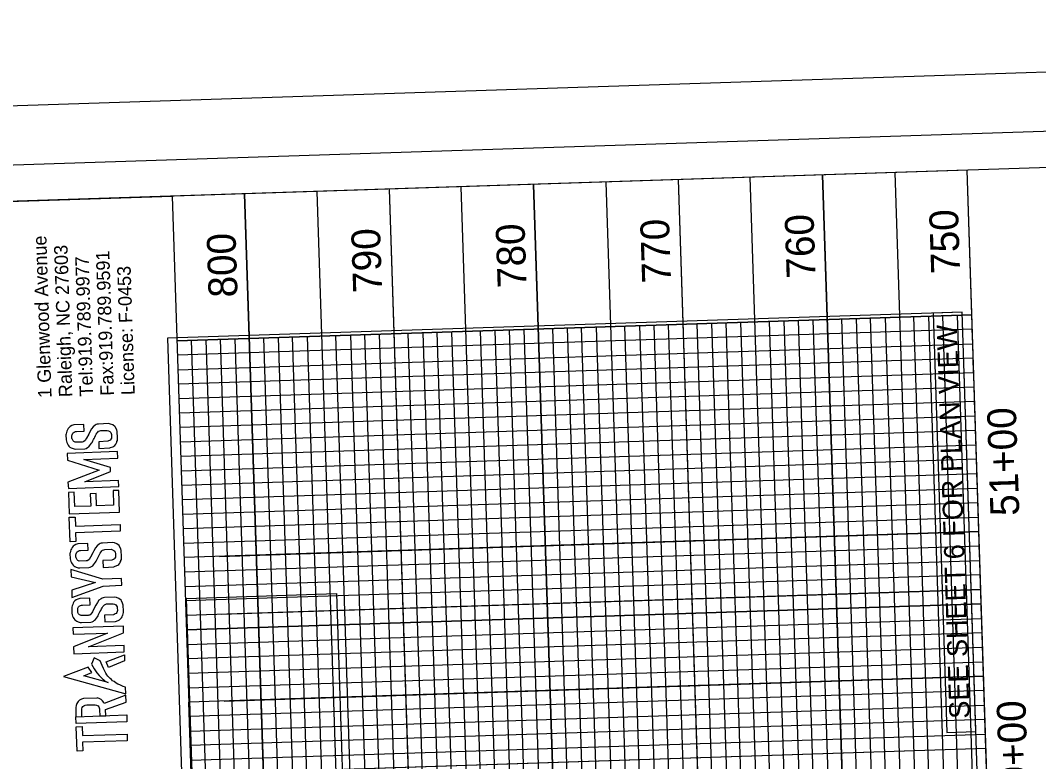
# Model space of a CAD drawing. Extents: x 1627318 to 1628473, y 762308 to 764226.
# Drawn here: x 1627516 to 1627868.1, y 763787.3 to 764043.5 of the extents above; entities that cross this region are included whole.
import ezdxf

# ---------------------------------------------------------------- set-up
doc = ezdxf.new("R2010")
doc.units = 0
for name, color, linetype in [('Exist Vertical Profile Horizontal Axis Label Major', 7, 'Continuous'), ('Exist Vertical Profile Vertical Axis Label', 7, 'Continuous'), ('Old_Level_2', 7, 'Continuous'), ('Prop DSN Text', 7, 'Continuous'), ('Prop Grid Mask', 7, 'Continuous'), ('Sheet DOT Grid CELL', 7, 'Continuous'), ('Sheet Layout Profile Border Port 1', 7, 'Continuous'), ('Sheet Plot Border Inside CELL', 7, 'Continuous'), ('Sheet Plot Border Outside CELL', 7, 'Continuous'), ('Sheet Profile CELL', 7, 'Continuous'), ('Sheet Profile Grid Major CELL', 7, 'Continuous'), ('Sheet Profile Grid Middle CELL', 7, 'Continuous'), ('Sheet Profile Grid Minor CELL', 7, 'Continuous')]:
    doc.layers.add(name, color=color, linetype=linetype)

msp = doc.modelspace()

# ---------------------------------------------------------------- linework, layer by layer
at = {"layer": 'Old_Level_2'}
for points in [[(1627511.12, 763780.74), (1627504.58, 763980.62), (1627568.5, 763982.71), (1627575.04, 763782.83)], [(1627538.04, 763901.44), (1627537.96, 763903.75), (1627534.48, 763903.63), (1627533.78, 763903.41), (1627533.2, 763903.11), (1627532.82, 763902.8), (1627532.48, 763902.42), (1627532.22, 763901.97), (1627532.06, 763901.54), (1627532.06, 763901.54), (1627531.88, 763901.08), (1627531.77, 763900.59), (1627531.7, 763900.27), (1627531.8, 763898.52), (1627531.9, 763897.99), (1627532, 763897.54), (1627532.25, 763897.09), (1627532.48, 763896.69), (1627532.77, 763896.31), (1627533.1, 763896.01), (1627533.47, 763895.78), (1627533.87, 763895.59), (1627534.58, 763895.36), (1627535.09, 763895.33), (1627538.26, 763895.43), (1627538.73, 763895.56), (1627539.22, 763895.81), (1627539.62, 763896.11), (1627539.92, 763896.42), (1627540.25, 763896.88), (1627540.58, 763897.34), (1627540.79, 763897.63), (1627541, 763898.12), (1627541.21, 763898.61), (1627541.45, 763899.01), (1627541.72, 763899.46), (1627541.97, 763900), (1627542.18, 763900.44), (1627542.48, 763900.88), (1627542.76, 763901.2), (1627542.99, 763901.46), (1627543.47, 763901.62), (1627543.76, 763901.73), (1627546, 763901.77), (1627546.49, 763901.62), (1627546.92, 763901.39), (1627547.22, 763901.07), (1627547.39, 763900.72), (1627547.47, 763900.38), (1627547.53, 763899.42), (1627547.45, 763899.1), (1627547.26, 763898.76), (1627547.08, 763898.43), (1627546.75, 763898.28), (1627546.42, 763898.12), (1627546.16, 763898), (1627543.05, 763897.86), (1627543.15, 763895.53), (1627546.86, 763895.69), (1627547.14, 763895.82), (1627547.99, 763896.12), (1627548.28, 763896.3), (1627548.59, 763896.56), (1627548.95, 763896.96), (1627549.13, 763897.27), (1627549.3, 763897.71), (1627549.36, 763897.87), (1627549.53, 763898.3), (1627549.56, 763898.84), (1627549.59, 763899.23), (1627549.47, 763901.37), (1627549.31, 763901.96), (1627548.9, 763902.78), (1627548.77, 763903.05), (1627547.96, 763903.65), (1627547.16, 763903.95), (1627546.45, 763904.09), (1627543.03, 763903.92), (1627542.56, 763903.9), (1627542.18, 763903.75), (1627541.84, 763903.55), (1627541.1, 763902.99), (1627540.56, 763902.26), (1627540.01, 763901.27), (1627539.6, 763900.51), (1627538.88, 763899.02), (1627538.34, 763898.25), (1627537.93, 763897.91), (1627537.65, 763897.82), (1627537.37, 763897.73), (1627534.94, 763897.7), (1627534.68, 763897.82), (1627534.42, 763897.93), (1627534.26, 763898.11), (1627534.06, 763898.33), (1627533.94, 763898.58), (1627533.83, 763898.84), (1627533.85, 763898.99), (1627533.78, 763899), (1627533.76, 763899.96), (1627533.86, 763900.24), (1627533.96, 763900.52), (1627534.06, 763900.8), (1627534.25, 763900.94), (1627534.52, 763901.13), (1627534.8, 763901.23), (1627535.07, 763901.33), (1627535.37, 763901.34)], [(1627543.17, 763888.07), (1627532.38, 763883.91), (1627532.55, 763881.7), (1627550, 763882.36), (1627549.92, 763884.46), (1627538.25, 763884.02), (1627547.13, 763887.58), (1627547.12, 763888.93), (1627537.89, 763891.7), (1627549.61, 763892.13), (1627549.52, 763894.41), (1627532.11, 763893.77), (1627532.2, 763891.47)], [(1627532.57, 763880.35), (1627532.81, 763872.97), (1627550.23, 763873.55), (1627549.98, 763881.02), (1627548.01, 763880.95), (1627548.18, 763875.91), (1627542.34, 763875.71), (1627542.2, 763879.93), (1627540.12, 763879.86), (1627540.27, 763875.61), (1627534.77, 763875.42), (1627534.6, 763880.43)], [(1627533.13, 763863.28), (1627532.84, 763871.75), (1627534.92, 763871.82), (1627535.02, 763868.71), (1627550.44, 763869.23), (1627550.51, 763866.88), (1627535, 763866.36), (1627535.1, 763863.39)], [(1627539.42, 763860.33), (1627539.34, 763862.64), (1627535.87, 763862.52), (1627535.17, 763862.31), (1627534.59, 763862.01), (1627534.21, 763861.69), (1627533.87, 763861.31), (1627533.6, 763860.86), (1627533.44, 763860.43), (1627533.44, 763860.43), (1627533.26, 763859.97), (1627533.15, 763859.48), (1627533.08, 763859.16), (1627533.18, 763857.41), (1627533.29, 763856.89), (1627533.38, 763856.43), (1627533.64, 763855.98), (1627533.86, 763855.58), (1627534.16, 763855.2), (1627534.48, 763854.9), (1627534.85, 763854.67), (1627535.25, 763854.48), (1627535.96, 763854.25), (1627536.48, 763854.22), (1627539.64, 763854.32), (1627540.11, 763854.45), (1627540.6, 763854.7), (1627541, 763855), (1627541.3, 763855.31), (1627541.63, 763855.77), (1627541.97, 763856.23), (1627542.18, 763856.53), (1627542.39, 763857.02), (1627542.6, 763857.51), (1627542.84, 763857.9), (1627543.11, 763858.35), (1627543.36, 763858.89), (1627543.56, 763859.33), (1627543.86, 763859.77), (1627544.15, 763860.09), (1627544.38, 763860.35), (1627544.85, 763860.52), (1627545.15, 763860.62), (1627547.38, 763860.66), (1627547.87, 763860.51), (1627548.3, 763860.28), (1627548.6, 763859.96), (1627548.78, 763859.61), (1627548.86, 763859.27), (1627548.91, 763858.32), (1627548.83, 763857.99), (1627548.65, 763857.65), (1627548.47, 763857.32), (1627548.13, 763857.17), (1627547.8, 763857.01), (1627547.54, 763856.89), (1627544.43, 763856.75), (1627544.54, 763854.42), (1627548.24, 763854.58), (1627548.52, 763854.71), (1627549.37, 763855.01), (1627549.66, 763855.19), (1627549.97, 763855.46), (1627550.33, 763855.85), (1627550.51, 763856.16), (1627550.68, 763856.6), (1627550.74, 763856.76), (1627550.91, 763857.19), (1627550.95, 763857.73), (1627550.97, 763858.12), (1627550.85, 763860.26), (1627550.69, 763860.85), (1627550.29, 763861.67), (1627550.15, 763861.94), (1627549.34, 763862.54), (1627548.54, 763862.85), (1627547.83, 763862.98), (1627544.41, 763862.81), (1627543.94, 763862.79), (1627543.57, 763862.65), (1627543.22, 763862.44), (1627542.48, 763861.88), (1627541.95, 763861.15), (1627541.4, 763860.16), (1627540.98, 763859.4), (1627540.26, 763857.91), (1627539.72, 763857.14), (1627539.31, 763856.8), (1627539.03, 763856.71), (1627538.75, 763856.63), (1627536.32, 763856.59), (1627536.06, 763856.71), (1627535.8, 763856.82), (1627535.64, 763857), (1627535.44, 763857.22), (1627535.33, 763857.48), (1627535.21, 763857.73), (1627535.23, 763857.88), (1627535.16, 763857.89), (1627535.14, 763858.85), (1627535.24, 763859.13), (1627535.34, 763859.41), (1627535.44, 763859.69), (1627535.63, 763859.83), (1627535.91, 763860.02), (1627536.18, 763860.12), (1627536.45, 763860.23), (1627536.76, 763860.23)], [(1627533.7, 763846.54), (1627533.79, 763844), (1627544.55, 763847.97), (1627551.08, 763848.22), (1627550.99, 763850.61), (1627544.51, 763850.36), (1627533.43, 763853.66), (1627533.58, 763851.17), (1627541.99, 763849.13)], [(1627540.05, 763841.47), (1627539.98, 763843.78), (1627536.5, 763843.66), (1627535.8, 763843.44), (1627535.22, 763843.14), (1627534.84, 763842.83), (1627534.5, 763842.45), (1627534.23, 763842), (1627534.07, 763841.57), (1627534.07, 763841.57), (1627533.9, 763841.11), (1627533.79, 763840.62), (1627533.72, 763840.3), (1627533.81, 763838.55), (1627533.92, 763838.02), (1627534.01, 763837.57), (1627534.27, 763837.12), (1627534.49, 763836.72), (1627534.79, 763836.33), (1627535.11, 763836.04), (1627535.49, 763835.81), (1627535.89, 763835.62), (1627536.59, 763835.39), (1627537.11, 763835.36), (1627540.28, 763835.46), (1627540.75, 763835.59), (1627541.23, 763835.84), (1627541.64, 763836.14), (1627541.94, 763836.45), (1627542.27, 763836.91), (1627542.6, 763837.37), (1627542.81, 763837.66), (1627543.02, 763838.15), (1627543.23, 763838.64), (1627543.47, 763839.04), (1627543.74, 763839.49), (1627543.99, 763840.03), (1627544.2, 763840.47), (1627544.5, 763840.91), (1627544.78, 763841.23), (1627545.01, 763841.49), (1627545.49, 763841.65), (1627545.78, 763841.76), (1627548.02, 763841.8), (1627548.51, 763841.65), (1627548.94, 763841.42), (1627549.24, 763841.1), (1627549.41, 763840.75), (1627549.49, 763840.41), (1627549.54, 763839.45), (1627549.46, 763839.13), (1627549.28, 763838.79), (1627549.1, 763838.46), (1627548.77, 763838.31), (1627548.44, 763838.15), (1627548.18, 763838.03), (1627545.07, 763837.89), (1627545.17, 763835.56), (1627548.88, 763835.72), (1627549.16, 763835.85), (1627550.01, 763836.15), (1627550.29, 763836.33), (1627550.6, 763836.59), (1627550.97, 763836.99), (1627551.15, 763837.3), (1627551.32, 763837.74), (1627551.38, 763837.9), (1627551.55, 763838.33), (1627551.58, 763838.87), (1627551.61, 763839.26), (1627551.48, 763841.4), (1627551.32, 763841.99), (1627550.92, 763842.8), (1627550.79, 763843.08), (1627549.98, 763843.68), (1627549.18, 763843.98), (1627548.46, 763844.11), (1627545.05, 763843.95), (1627544.57, 763843.93), (1627544.2, 763843.78), (1627543.85, 763843.58), (1627543.11, 763843.02), (1627542.58, 763842.29), (1627542.03, 763841.3), (1627541.61, 763840.54), (1627540.9, 763839.05), (1627540.36, 763838.28), (1627539.95, 763837.94), (1627539.67, 763837.85), (1627539.39, 763837.76), (1627536.95, 763837.73), (1627536.7, 763837.85), (1627536.44, 763837.96), (1627536.28, 763838.13), (1627536.08, 763838.36), (1627535.96, 763838.61), (1627535.84, 763838.87), (1627535.87, 763839.02), (1627535.79, 763839.03), (1627535.78, 763839.99), (1627535.88, 763840.27), (1627535.98, 763840.55), (1627536.08, 763840.83), (1627536.27, 763840.97), (1627536.54, 763841.16), (1627536.81, 763841.26), (1627537.09, 763841.36), (1627537.39, 763841.37)], [(1627534.43, 763824.58), (1627551.88, 763825.17), (1627551.81, 763827.4), (1627539.53, 763826.99), (1627551.68, 763831.84), (1627551.58, 763834.09), (1627534.09, 763833.49), (1627534.16, 763831.32), (1627546.14, 763831.72), (1627534.35, 763826.93)], [(1627546.48, 763819.81), (1627545.66, 763821.71), (1627552.01, 763824.18), (1627552.01, 763822.08)], [(1627530.87, 763816.69), (1627552.41, 763810.73), (1627552.33, 763812.95), (1627551.48, 763813.26), (1627550.3, 763813.8), (1627549.66, 763814.09), (1627549.11, 763814.44), (1627548.34, 763814.94), (1627547.86, 763815.25), (1627547.45, 763815.62), (1627547.05, 763815.99), (1627546.53, 763816.46), (1627546.25, 763816.86), (1627545.91, 763817.26), (1627545.57, 763817.81), (1627545.27, 763818.29), (1627544.66, 763819.49), (1627544.22, 763820.48), (1627543.61, 763822.1), (1627541.43, 763823.17), (1627540.54, 763820.96), (1627541.48, 763819.36), (1627542.43, 763818.01), (1627543.26, 763817.06), (1627543.7, 763816.55), (1627544.29, 763816.03), (1627544.87, 763815.52), (1627545.31, 763815.13), (1627545.97, 763814.78), (1627546.34, 763814.58), (1627537.88, 763816.93), (1627540.73, 763818.02), (1627539.41, 763819.88)], [(1627537.26, 763802.87), (1627537.18, 763805.25), (1627537.22, 763805.56), (1627537.37, 763805.96), (1627537.58, 763806.29), (1627537.85, 763806.53), (1627538.17, 763806.7), (1627538.42, 763806.83), (1627539, 763806.85), (1627541.49, 763806.94), (1627541.82, 763806.89), (1627542.27, 763806.82), (1627542.57, 763806.7), (1627542.83, 763806.51), (1627543.06, 763806.25), (1627543.22, 763805.83), (1627543.28, 763805.5), (1627543.33, 763805.18), (1627543.41, 763803.07), (1627545.51, 763803.15), (1627545.43, 763805.26), (1627552.51, 763807.86), (1627552.41, 763810.27), (1627544.96, 763807.38), (1627544.82, 763807.75), (1627544.4, 763808.28), (1627543.85, 763808.75), (1627543.21, 763809.07), (1627542.57, 763809.27), (1627542.38, 763809.25), (1627537.81, 763809.14), (1627537.08, 763808.91), (1627536.41, 763808.53), (1627535.95, 763808.1), (1627535.5, 763807.39), (1627535.3, 763806.7), (1627535.09, 763806.02), (1627535.11, 763805.61), (1627535.18, 763802.8)], [(1627535.26, 763800.48), (1627535.18, 763802.8), (1627552.73, 763803.39), (1627552.81, 763801.07)], [(1627535.57, 763790.87), (1627535.28, 763799.33), (1627537.35, 763799.4), (1627537.46, 763796.29), (1627552.87, 763796.81), (1627552.95, 763794.46), (1627537.43, 763793.94), (1627537.53, 763790.97)]]:
    msp.add_lwpolyline(points, close=True, dxfattribs=at)
at = {"layer": 'Prop Grid Mask'}
for points in [[(1627831.66, 763942.29), (1627836.4, 763797.36), (1627846.39, 763797.69), (1627841.65, 763942.61)], [(1627575.85, 763769.46), (1627573.42, 763843.69), (1627625.24, 763845.39), (1627627.67, 763771.15)]]:
    msp.add_lwpolyline(points, close=True, dxfattribs=at)
at = {"layer": 'Sheet DOT Grid CELL'}
for p, q in [((1627793.38, 763990.08), (1627842.42, 762490.88)), ((1627693.43, 763986.81), (1627742.47, 762487.61)), ((1627743.4, 763988.44), (1627792.44, 762489.24)), ((1627593.48, 763983.54), (1627642.52, 762484.34)), ((1627643.46, 763985.17), (1627692.5, 762485.97)), ((1627844.99, 763941.74), (1627570.13, 763932.75)), ((1627846.62, 763891.76), (1627571.77, 763882.77)), ((1627848.26, 763841.79), (1627573.4, 763832.8)), ((1627849.89, 763791.82), (1627487.63, 763779.97))]:
    msp.add_line(p, q, dxfattribs=at)
at = {"layer": 'Sheet Layout Profile Border Port 1'}
msp.add_lwpolyline([(1627387.69, 762527.01), (1627887.42, 762543.36), (1627841.65, 763942.61), (1627566.8, 763933.62), (1627571.7, 763783.65), (1627346.82, 763776.3), (1627347.71, 763777.21)], close=True, dxfattribs=at)
msp.add_lwpolyline([(1627551.99, 762531.4), (1627890.76, 762542.49), (1627844.99, 763941.74), (1627570.13, 763932.75)], dxfattribs=at)
at = {"layer": 'Sheet Plot Border Inside CELL'}
msp.add_lwpolyline([(1628449.68, 762356.66), (1628395.2, 764022.27), (1627340.66, 763987.77), (1627395.14, 762322.16)], close=True, dxfattribs=at)
at = {"layer": 'Sheet Plot Border Outside CELL'}
msp.add_lwpolyline([(1628472.54, 762344.4), (1628416.96, 764043.49), (1627317.55, 764007.53), (1627373.13, 762308.44)], close=True, dxfattribs=at)
at = {"layer": 'Sheet Profile CELL'}
msp.add_line((1627892.39, 762492.51), (1627843.35, 763991.71), dxfattribs=at)
msp.add_lwpolyline([(1627343.62, 763975.36), (1627392.66, 762476.17), (1628442.1, 762510.49), (1628393.06, 764009.69)], close=True, dxfattribs=at)
at = {"layer": 'Sheet Profile Grid Major CELL'}
for points in [[(1627570.13, 763932.75), (1627844.99, 763941.74), (1627843.35, 763991.71), (1627493.54, 763980.27)], [(1627743.4, 763988.44), (1627792.44, 762489.24), (1627792.44, 762489.24), (1627842.42, 762490.88), (1627793.38, 763990.08)], [(1627643.46, 763985.17), (1627692.5, 762485.97), (1627742.47, 762487.61), (1627693.43, 763986.81)], [(1627550.05, 763782.01), (1627592.55, 762482.7), (1627642.52, 762484.34), (1627593.48, 763983.54)], [(1627573.4, 763832.8), (1627848.26, 763841.79), (1627846.62, 763891.76), (1627846.62, 763891.76), (1627571.77, 763882.77)], [(1627867.87, 763242.11), (1627866.24, 763292.08), (1627366.5, 763275.74), (1627364.87, 763325.71), (1627864.6, 763342.06), (1627862.97, 763392.03), (1627363.23, 763375.68), (1627361.6, 763425.66), (1627861.33, 763442), (1627859.7, 763491.98), (1627359.96, 763475.63), (1627358.33, 763525.6), (1627858.06, 763541.95), (1627856.43, 763591.92), (1627356.7, 763575.58), (1627355.06, 763625.55), (1627854.79, 763641.9), (1627853.16, 763691.87), (1627353.43, 763675.52), (1627351.79, 763725.5), (1627851.52, 763741.84), (1627849.89, 763791.82), (1627350.16, 763775.47), (1627349.3, 763801.76)]]:
    msp.add_lwpolyline(points, dxfattribs=at)
at = {"layer": 'Sheet Profile Grid Middle CELL'}
for points in [[(1627718.42, 763987.62), (1627767.46, 762488.43), (1627817.43, 762490.06), (1627768.39, 763989.26)], [(1627818.36, 763990.89), (1627867.4, 762491.69)], [(1627618.47, 763984.35), (1627667.51, 762485.16), (1627717.48, 762486.79), (1627668.44, 763985.99)], [(1627584.78, 763858.19), (1627847.44, 763866.78), (1627845.8, 763916.75), (1627570.95, 763907.76)], [(1627586.41, 763808.21), (1627849.07, 763816.8), (1627847.44, 763866.78), (1627572.58, 763857.79)], [(1627867.05, 763267.1), (1627865.42, 763317.07), (1627365.69, 763300.72), (1627364.05, 763350.7), (1627863.78, 763367.04), (1627862.15, 763417.02), (1627362.42, 763400.67), (1627360.78, 763450.64), (1627860.51, 763466.99), (1627858.88, 763516.96), (1627359.15, 763500.62), (1627357.51, 763550.59), (1627857.25, 763566.94), (1627855.61, 763616.91), (1627355.88, 763600.56), (1627354.24, 763650.54), (1627853.98, 763666.88), (1627852.34, 763716.86), (1627352.61, 763700.51), (1627350.97, 763750.48), (1627850.71, 763766.83), (1627849.07, 763816.8), (1627574.22, 763807.81)], [(1627525.07, 763781.14), (1627567.56, 762481.89), (1627617.54, 762483.52), (1627574.22, 763807.81)]]:
    msp.add_lwpolyline(points, dxfattribs=at)
at = {"layer": 'Sheet Profile Grid Minor CELL'}
for p, q in [((1627790.02, 763939.94), (1627835.78, 762540.69)), ((1627845.78, 762541.01), (1627800.01, 763940.27)), ((1627805.01, 763940.43), (1627850.78, 762541.18)), ((1627855.77, 762541.34), (1627810, 763940.59)), ((1627815, 763940.76), (1627860.77, 762541.5)), ((1627870.77, 762541.83), (1627825, 763941.08)), ((1627829.99, 763941.25), (1627875.76, 762541.99)), ((1627880.76, 762542.16), (1627834.99, 763941.41)), ((1627680.07, 763936.34), (1627725.84, 762537.09)), ((1627730.84, 762537.25), (1627685.07, 763936.51)), ((1627690.07, 763936.67), (1627735.84, 762537.42)), ((1627745.83, 762537.74), (1627700.06, 763937)), ((1627705.06, 763937.16), (1627750.83, 762537.91)), ((1627755.83, 762538.07), (1627710.06, 763937.32)), ((1627715.06, 763937.49), (1627760.82, 762538.24)), ((1627770.82, 762538.56), (1627725.05, 763937.81)), ((1627730.05, 763937.98), (1627775.82, 762538.73)), ((1627735.04, 763938.14), (1627780.81, 762538.89)), ((1627740.04, 763938.3), (1627785.81, 762539.05)), ((1627795.81, 762539.38), (1627750.04, 763938.63)), ((1627755.03, 763938.79), (1627800.8, 762539.54)), ((1627805.8, 762539.71), (1627760.03, 763938.96)), ((1627765.03, 763939.12), (1627810.8, 762539.87)), ((1627820.79, 762540.2), (1627775.02, 763939.45)), ((1627780.02, 763939.61), (1627825.79, 762540.36)), ((1627830.79, 762540.52), (1627785.02, 763939.78)), ((1627580.13, 763933.07), (1627625.9, 762533.82)), ((1627630.89, 762533.99), (1627585.12, 763933.24)), ((1627590.12, 763933.4), (1627635.89, 762534.15)), ((1627645.89, 762534.48), (1627600.12, 763933.73)), ((1627605.11, 763933.89), (1627650.88, 762534.64)), ((1627655.88, 762534.8), (1627610.11, 763934.05)), ((1627615.11, 763934.22), (1627660.88, 762534.97)), ((1627670.87, 762535.29), (1627625.1, 763934.54)), ((1627630.1, 763934.71), (1627675.87, 762535.46)), ((1627680.87, 762535.62), (1627635.1, 763934.87)), ((1627640.1, 763935.03), (1627685.86, 762535.78)), ((1627695.86, 762536.11), (1627650.09, 763935.36)), ((1627655.09, 763935.53), (1627700.86, 762536.27)), ((1627705.85, 762536.44), (1627660.08, 763935.69)), ((1627665.08, 763935.85), (1627710.85, 762536.6)), ((1627720.85, 762536.93), (1627675.08, 763936.18))]:
    msp.add_line(p, q, dxfattribs=at)
for points in [[(1627839.99, 763941.57), (1627885.76, 762542.32)], [(1627570.46, 763922.75), (1627845.31, 763931.74), (1627845.15, 763936.74), (1627570.3, 763927.75)], [(1627570.04, 763782.61), (1627610.9, 762533.33), (1627620.9, 762533.66), (1627575.13, 763932.91)], [(1627570.79, 763912.76), (1627845.64, 763921.75), (1627845.48, 763926.74), (1627570.62, 763917.75)], [(1627571.28, 763897.76), (1627846.13, 763906.76), (1627845.97, 763911.75), (1627571.11, 763902.76)], [(1627571.6, 763887.77), (1627846.46, 763896.76), (1627846.29, 763901.76), (1627571.44, 763892.77)], [(1627572.09, 763872.78), (1627846.95, 763881.77), (1627846.78, 763886.77), (1627571.93, 763877.78)], [(1627572.42, 763862.78), (1627847.27, 763871.77), (1627847.11, 763876.77), (1627572.26, 763867.78)], [(1627572.91, 763847.79), (1627847.76, 763856.78), (1627847.6, 763861.78), (1627572.75, 763852.79)], [(1627585.43, 763838.2), (1627848.09, 763846.79), (1627847.93, 763851.78), (1627573.08, 763842.79)], [(1627573.57, 763827.78), (1627848.37, 763836.69), (1627848.21, 763841.69), (1627848.09, 763846.79), (1627573.24, 763837.8)], [(1627574.06, 763812.81), (1627848.91, 763821.8), (1627848.91, 763821.8), (1627848.75, 763826.8), (1627848.58, 763831.8), (1627573.73, 763822.81)], [(1627573.89, 763817.81), (1627848.75, 763826.8)], [(1627574.55, 763797.82), (1627849.4, 763806.81), (1627849.24, 763811.81), (1627574.38, 763802.82)], [(1627574.87, 763787.82), (1627849.73, 763796.81), (1627849.56, 763801.81), (1627574.71, 763792.82)]]:
    msp.add_lwpolyline(points, dxfattribs=at)

# ---------------------------------------------------------------- texts
at = {"layer": 'Exist Vertical Profile Horizontal Axis Label Major'}
for s, p in [('51+00', (1627861.46, 763872.35)), ('50+00', (1627864.77, 763771.05))]:
    msp.add_text(s, height=10, rotation=91.8735, dxfattribs=at).set_placement(p)
at = {"layer": 'Exist Vertical Profile Vertical Axis Label'}
for s, p in [('760', (1627790.99, 763954.39)), ('750', (1627840.96, 763956.03)), ('780', (1627691.04, 763951.13)), ('770', (1627741.01, 763952.76)), ('800', (1627591.09, 763947.86)), ('790', (1627641.07, 763949.49))]:
    msp.add_text(s, height=10, rotation=91.8735, dxfattribs=at).set_placement(p)
at = {"layer": 'Old_Level_2'}
for s, p in [('1 Glenwood Avenue', (1627526.77, 763913.1)), ('Raleigh, NC 27603', (1627533.96, 763913.34)), ('Tel:919.789.9977 ', (1627541.15, 763913.57)), ('Fax:919.789.9591', (1627548.34, 763913.81)), ('License: F-0453', (1627555.53, 763914.04))]:
    msp.add_text(s, height=4.6576, rotation=91.8735, dxfattribs=at).set_placement(p)
at = {"layer": 'Prop DSN Text'}
msp.add_text('SEE SHEET 6 FOR PLAN VIEW', height=7, rotation=91.8735, dxfattribs=at).set_placement((1627844.29, 763802.2))

doc.saveas('drawing.dxf')
